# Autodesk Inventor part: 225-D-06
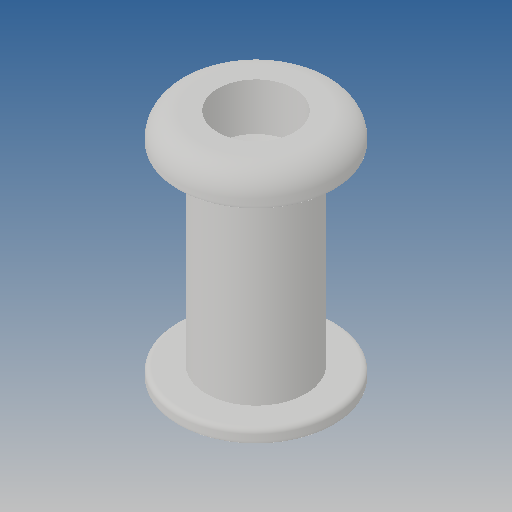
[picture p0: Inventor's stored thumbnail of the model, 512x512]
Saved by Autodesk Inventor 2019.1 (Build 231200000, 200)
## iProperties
Created: 2011-05
Part Number: 225-D-06
Material: Ogólny
Document SubType Name: Modeling
Designer: CADENGINEERING4
Density: 1 g/cm^3
Appearance: Domyślna
Author: CADENGINEERING4
Revision Number: ÈÎºÎ
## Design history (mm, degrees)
feature "Ðý×ª1"
node "Bryła1"
